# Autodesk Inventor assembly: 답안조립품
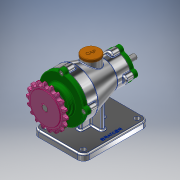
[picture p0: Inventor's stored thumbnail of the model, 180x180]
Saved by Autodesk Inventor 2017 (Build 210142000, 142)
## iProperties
Part Number: 답안조립품
Material: 일반
Document SubType Name: Assembly
Designer: 7-1
Author: 7-1
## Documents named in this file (15)
- C:\Users\7-1\Desktop\701206V1012\답안조립품.iam
- C:\Users\7-1\Desktop\701206V1012\본체.ipt
- C:\Users\7-1\Desktop\701206V1012\개스킷 A.ipt
- C:\Users\7-1\Desktop\701206V1012\개스킷 B.ipt
- C:\Users\7-1\Desktop\701206V1012\뒤커버.ipt
- C:\Users\7-1\Desktop\701206V1012\마개.ipt
- C:\Users\7-1\Desktop\701206V1012\베어링 6200.ipt
- C:\Users\7-1\Desktop\701206V1012\베어링 6203.ipt
- C:\Users\7-1\Desktop\701206V1012\볼트 M5.ipt
- C:\Users\7-1\Desktop\701206V1012\스프로킷.ipt
- C:\Users\7-1\Desktop\701206V1012\앞커버.ipt
- C:\Users\7-1\Desktop\701206V1012\오일 실 10 20 7.ipt
- C:\Users\7-1\Desktop\701206V1012\오일 실 17 30 8.ipt
- C:\Users\7-1\Desktop\701206V1012\축.ipt
- C:\Users\7-1\Desktop\701206V1012\키 4x4x14.ipt
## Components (2 placed, 2 different names)
1. 개스킷 A:1
2. 개스킷 B:1
